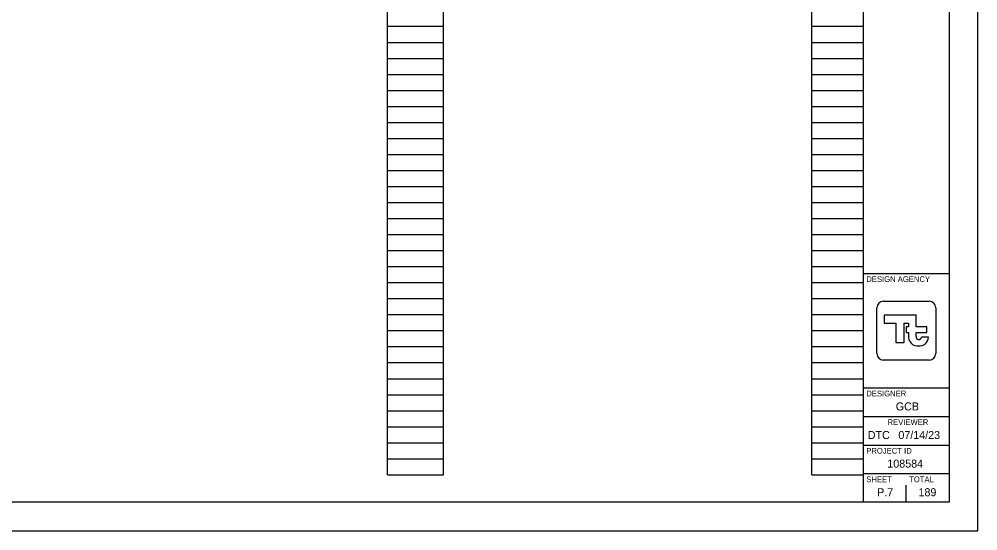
# Model space of a CAD drawing. Extents: x 0 to 55.4, y -1.6 to 22.
# Drawn here: x 17.24 to 34, y 0 to 8.95 of the extents above; entities that cross this region are included whole.
import ezdxf

# ---------------------------------------------------------------- set-up
doc = ezdxf.new("R2010")
doc.units = 0
for name, color, linetype in [('SH_Border', 7, 'Continuous'), ('SH_Cut_Line', 7, 'Continuous'), ('SH_Data', 7, 'Continuous')]:
    doc.layers.add(name, color=color, linetype=linetype)

msp = doc.modelspace()

# ---------------------------------------------------------------- linework, layer by layer
at = {"layer": 'SH_Border'}
for p, q in [((32, 0.5), (32, 21.5)), ((32, 4.5), (33.5, 4.5)), ((32, 2.5), (33.5, 2.5)), ((32, 2), (33.5, 2)), ((32, 1.5), (33.5, 1.5)), ((32, 1), (33.5, 1))]:
    msp.add_line(p, q, dxfattribs=at)
msp.add_lwpolyline([(1.5, 21.5), (33.5, 21.5), (33.5, 0.5), (1.5, 0.5)], close=True, dxfattribs=at)
at = {"layer": 'SH_Cut_Line'}
msp.add_lwpolyline([(0, 0), (34, 0), (34, 22), (0, 22)], close=True, dxfattribs=at)
at = {"layer": 'SH_Data'}
for p, q in [((23.68, 0.98), (23.68, 21.14)), ((24.66, 0.98), (24.66, 21.14)), ((31.1, 0.98), (31.1, 21.14)), ((32, 0.98), (32, 21.14)), ((23.68, 8.82), (24.66, 8.82)), ((31.1, 8.82), (32, 8.82)), ((23.68, 8.54), (24.66, 8.54)), ((31.1, 8.54), (32, 8.54)), ((23.68, 8.26), (24.66, 8.26)), ((31.1, 8.26), (32, 8.26)), ((23.68, 7.98), (24.66, 7.98)), ((31.1, 7.98), (32, 7.98)), ((23.68, 7.7), (24.66, 7.7)), ((31.1, 7.7), (32, 7.7)), ((23.68, 7.42), (24.66, 7.42)), ((31.1, 7.42), (32, 7.42)), ((23.68, 7.14), (24.66, 7.14)), ((31.1, 7.14), (32, 7.14)), ((23.68, 6.86), (24.66, 6.86)), ((31.1, 6.86), (32, 6.86)), ((23.68, 6.58), (24.66, 6.58)), ((31.1, 6.58), (32, 6.58)), ((23.68, 6.3), (24.66, 6.3)), ((31.1, 6.3), (32, 6.3)), ((23.68, 6.02), (24.66, 6.02)), ((31.1, 6.02), (32, 6.02)), ((23.68, 5.74), (24.66, 5.74)), ((31.1, 5.74), (32, 5.74)), ((23.68, 5.46), (24.66, 5.46)), ((31.1, 5.46), (32, 5.46)), ((23.68, 5.18), (24.66, 5.18)), ((31.1, 5.18), (32, 5.18)), ((23.68, 4.9), (24.66, 4.9)), ((31.1, 4.9), (32, 4.9)), ((23.68, 4.62), (24.66, 4.62)), ((31.1, 4.62), (32, 4.62)), ((23.68, 4.34), (24.66, 4.34)), ((31.1, 4.34), (32, 4.34)), ((23.68, 4.06), (24.66, 4.06)), ((31.1, 4.06), (32, 4.06)), ((23.68, 3.78), (24.66, 3.78)), ((31.1, 3.78), (32, 3.78)), ((23.68, 3.5), (24.66, 3.5)), ((31.1, 3.5), (32, 3.5)), ((32.75, 3.5), (32.75, 3.5)), ((32.791, 3.415), (32.791, 3.415)), ((33.136, 3.385), (33.015, 3.385)), ((23.68, 3.22), (24.66, 3.22)), ((31.1, 3.22), (32, 3.22)), ((23.68, 2.94), (24.66, 2.94)), ((31.1, 2.94), (32, 2.94)), ((23.68, 2.66), (24.66, 2.66)), ((31.1, 2.66), (32, 2.66)), ((23.68, 2.38), (24.66, 2.38)), ((31.1, 2.38), (32, 2.38)), ((23.68, 2.1), (24.66, 2.1)), ((31.1, 2.1), (32, 2.1)), ((23.68, 1.82), (24.66, 1.82)), ((31.1, 1.82), (32, 1.82)), ((23.68, 1.54), (24.66, 1.54)), ((31.1, 1.54), (32, 1.54)), ((23.68, 1.26), (24.66, 1.26)), ((31.1, 1.26), (32, 1.26)), ((23.68, 0.98), (24.66, 0.98)), ((31.1, 0.98), (32, 0.98)), ((32.375, 0.675), (32.375, 0.675)), ((32.75, 0.5), (32.75, 0.8))]:
    msp.add_line(p, q, dxfattribs=at)
for points in [[(32.236, 3.099), (32.236, 3.901)], [(32.348, 4.014), (33.152, 4.014)], [(33.264, 3.901), (33.264, 3.099)], [(32.922, 3.399), (32.922, 3.47), (33.107, 3.47), (33.107, 3.568), (32.922, 3.568), (32.922, 3.768), (32.361, 3.768), (32.361, 3.632), (32.566, 3.632), (32.566, 3.294), (32.715, 3.294), (32.715, 3.63), (32.79, 3.63), (32.79, 3.568), (32.748, 3.568), (32.748, 3.47), (32.79, 3.47), (32.79, 3.415), (32.791, 3.415)], [(33.152, 2.986), (32.348, 2.986)]]:
    msp.add_lwpolyline(points, dxfattribs=at)
for centre, radius, start, end in [((32.348, 3.901), 0.113, 90, 180), ((33.152, 3.901), 0.113, 360, 90), ((32.949, 3.392), 0.16, 171.8856, 274.8323), ((32.968, 3.392), 0.0473, 171.8856, 350.9243), ((32.976, 3.392), 0.16, 265.1677, 357.3201), ((32.348, 3.099), 0.113, 180, 270), ((33.152, 3.099), 0.113, 270, 360)]:
    msp.add_arc(centre, radius, start, end, dxfattribs=at)

# ---------------------------------------------------------------- texts
for s, height, p in [('DESIGN AGENCY', 0.1, (32.05, 4.35)), ('DESIGNER', 0.1, (32.05, 2.35)), ('GCB', 0.14, (32.566, 2.105)), ('REVIEWER', 0.1, (32.422, 1.85)), ('DTC', 0.14, (32.076, 1.605)), ('07/14/23', 0.14, (32.611, 1.605)), ('PROJECT ID', 0.1, (32.05, 1.35)), ('108584', 0.14, (32.418, 1.105)), ('SHEET', 0.1, (32.05, 0.85)), ('TOTAL', 0.1, (32.8, 0.85)), ('P.7', 0.14, (32.239, 0.605)), ('189', 0.14, (32.963, 0.605))]:
    msp.add_text(s, height=height, dxfattribs=at).set_placement(p)

doc.saveas('drawing.dxf')
